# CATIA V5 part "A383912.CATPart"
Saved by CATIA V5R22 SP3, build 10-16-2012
Part number: EPXBE34SA
Revision: -
Definition: A383912
Nomenclature: INSERT, SOCKET RECT CONNECTOR, EPX SERIES GP
Source: bought
Description: INSERT, SOCKET RECT CONNECTOR, EPX SERIES GP
Publications: "Logical Termination.1", "Logical Pin.1", "CaCP", "CaCP_generated(CaCP)", "Line.1_generated(CaCP)", "Line.2_generated(CaCP)", "BCP", "BCP_generated(BCP)", "Face_generated(BCP)"
Material "Density=.0450": density 1245.6 kg/m3
Bounding box of the stored display mesh (mm): x -13.526 to 13.526, y -6.007 to 6.548, z -18.999 to 9.398
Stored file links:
  C:\Users\u305772\OneDrive - Gulfstream Aerospace\AD PAG\Harness\A383912.CATPart
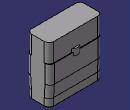
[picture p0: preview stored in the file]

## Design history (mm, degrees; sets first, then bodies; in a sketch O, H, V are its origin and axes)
Parameters
  PartNumber = "EPXBE34SA"
  OtherKeywords = "INSERT, SOCKET RECT CONNECTOR, EPX SERIES GP"
  Comments = "INSERT, SOCKET RECT CONNECTOR, EPX SERIES GP"
  CAGECode = "F0987"
  WeightComment = "CALCULATED FROM CATIA"
  WeightSource = "Calculated"
  Volume = 8.7849e-06 (volume) {= smartVolume(Body1)}
  Density = 1245.6 (density)
  Weight = 0.02019
Set1
  Point1 "CaCP": (0, 0, 0)
  Point2 "BCP": type OnPlane, Support face of Pad1 from Sketch1.L7, H 0, V 0, Direction (1, 0, 0)
  Line1: type PtDir, RefPoint Point1, Direction (0, 0, 1), Start 0, End 6.35
  Line2: type PtDir, RefPoint Point1, Direction (0, 1, 0), Start 0, End 6.35
Body1 (main body)
  Sketch1 on yz-plane, origin (0, 0, 0), H (0, 1, 0), V (0, 0, 1)
    point P1 (0, 9.398)
    line L1 (-5.6515, 9.398) -> (5.6515, 9.398)
    line L2 (5.6515, 9.398) -> (5.6515, 0)
    point P3 (5.6515, 0)
    line L3 (5.6515, 0) -> (6.0071, 0)
    point P4 (6.0071, 0)
    line L4 (6.0071, 0) -> (6.0071, -9.2202)
    point P5 (6.0071, -9.2202)
    line L5 (6.0071, -9.2202) -> (5.6515, -15.2654)
    point P6 (5.6515, -15.2654)
    line L6 (5.6515, -15.2654) -> (5.6515, -18.9992)
    line L7 (5.6515, -18.9992) -> (-5.6515, -18.9992)
    point P8 (0, -18.9992)
    construction line L8 (0, -18.9992) -> (0, 9.398)
    point P9 (-5.6515, 0)
    line L9 (-5.6515, 9.398) -> (-5.6515, 0)
    point P10 (-6.0071, 0)
    line L10 (-5.6515, 0) -> (-6.0071, 0)
    point P11 (-6.0071, -9.2202)
    line L11 (-6.0071, 0) -> (-6.0071, -9.2202)
    point P12 (-5.6515, -15.2654)
    line L12 (-6.0071, -9.2202) -> (-5.6515, -15.2654)
    line L13 (-5.6515, -15.2654) -> (-5.6515, -18.9992)
    distance L3 L1 = 9.398
    distance P6 L7 = 3.7338
    distance P5 L7 = 9.779
    distance L6 L13 = 11.303
    distance L4 L11 = 12.0142
    distance L3 L7 = 18.9992
    distance L1 L7 = 28.3972 (reference)
    coincidence: P1 V, P6 L2, P8 V, P1 L1, L3 H, P8 L7
    horizontal: L1 H, L3 H, L7 H
    vertical: L2 V, L4 V, L6 V, L8 V
    symmetry: P3 P9 L8, L2 L9 L8, P4 P10 L8, L3 L10 L8, P5 P11 L8, L4 L11 L8, P6 P12 L8, L5 L12 L8, L6 L13 L8
  Pad1: profile Sketch1, direction (1, 0, 0), length 13.5255, mirrored extent
  Fillet1: radius 2.3876, on edge [start face of Pad1 | face of Pad1 from Sketch1.L2]; edge [start face of Pad1 | face of Pad1 from Sketch1.L9]; edge [face of Pad1 from Sketch1.L9 | end face of Pad1]; edge [face of Pad1 from Sketch1.L2 | end face of Pad1]; edge [start face of Pad1 | face of Pad1 from Sketch1.L13]; edge [start face of Pad1 | face of Pad1 from Sketch1.L6]; edge [face of Pad1 from Sketch1.L6 | end face of Pad1]; edge [face of Pad1 from Sketch1.L13 | end face of Pad1]; edge [face of Pad1 from Sketch1.L12 | end face of Pad1]; edge [face of Pad1 from Sketch1.L5 | end face of Pad1]; edge [start face of Pad1 | face of Pad1 from Sketch1.L5]; edge [start face of Pad1 | face of Pad1 from Sketch1.L12]; edge [start face of Pad1 | face of Pad1 from Sketch1.L11]; edge [start face of Pad1 | face of Pad1 from Sketch1.L4]; edge [face of Pad1 from Sketch1.L4 | end face of Pad1]; edge [face of Pad1 from Sketch1.L11 | end face of Pad1]
  Sketch2 on face of Pad1 from Sketch1.L3, origin (0, 0, 0), H (1, 0, 0), V (0, 1, 0)
    circle A1 centre (0, 3.9688) radius 2.5797
    point P1 (0, 3.9688)
    radius A1 = 2.5797
    distance H P1 = 3.9688
    coincidence: P1 V
  Pad2: profile Sketch2, direction (0, 0, 1), length 1.5875, mirrored extent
